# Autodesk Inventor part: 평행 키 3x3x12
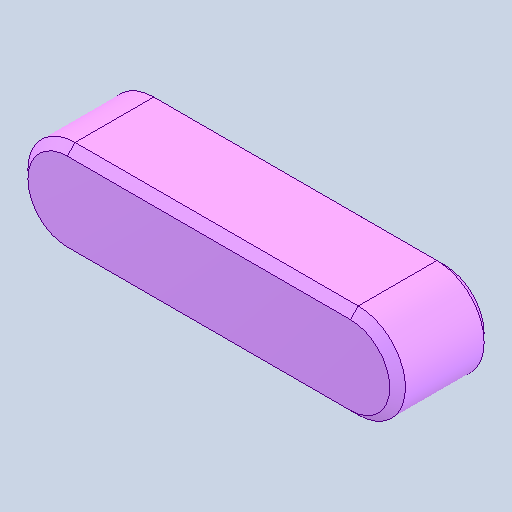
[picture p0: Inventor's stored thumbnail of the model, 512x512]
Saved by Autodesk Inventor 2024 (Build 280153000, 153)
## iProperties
Created: 2025-10
Part Number: 평행 키 3x3x12
Material: 강철, 연강
Description: 키 및 해당 키홈
Document SubType Name: Modeling
Designer: EDU03
Density: 7.85 g/cm^3
Appearance: 기본값
Author: jhkim
Sending System: Autodesk Inventor 2026
Preprocessor: ST-DEVELOPER v20.1
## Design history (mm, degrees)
feature "Solid1"
node "솔리드1"
